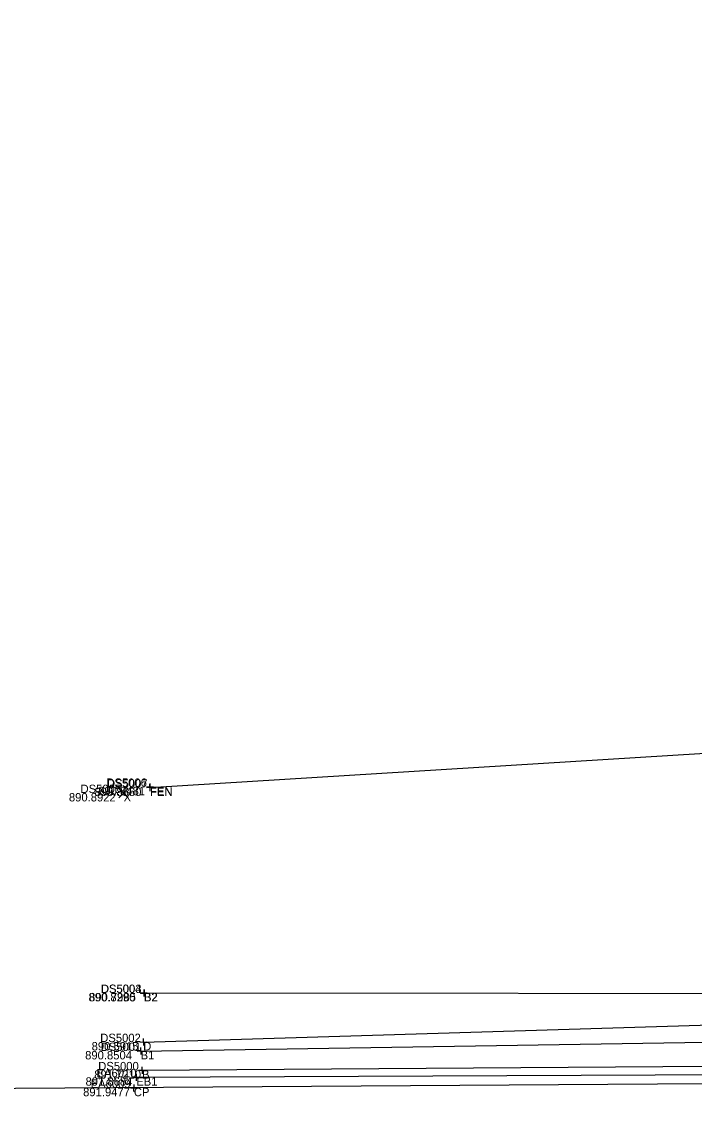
# Model space of a CAD drawing. Extents: x 179044 to 189691, y 286531 to 301257.
# Drawn here: x 179547.2 to 179643.4, y 300591.8 to 300746 of the extents above; entities that cross this region are included whole.
import ezdxf

# ---------------------------------------------------------------- set-up
doc = ezdxf.new("R2010")
doc.units = 0
for name, color, linetype in [('DR_X_Ditch', 7, 'Continuous'), ('PV_X_EOP', 7, 'Continuous'), ('PV_X_Shoulder_Aggregate', 7, 'Continuous'), ('RD_X_Fence', 7, 'Continuous'), ('SV_X_Break_Lines', 7, 'Continuous'), ('SV_X_Random_Point', 7, 'Continuous'), ('SV_X_Shot_Marker', 7, 'Continuous'), ('SV_X_Text_Comment', 7, 'Continuous'), ('SV_X_Text_Elevation', 7, 'Continuous'), ('SV_X_Text_Name', 7, 'Continuous')]:
    doc.layers.add(name, color=color, linetype=linetype)

msp = doc.modelspace()

# ---------------------------------------------------------------- linework, layer by layer
at = {"layer": 'DR_X_Ditch'}
msp.add_lwpolyline([(179564.56, 300599.96), (179672.34, 300603.26), (179771.17, 300605.49), (179880.34, 300606.44), (179984.94, 300607.33), (180077.95, 300608.96), (180127.19, 300616.84), (180132.04, 300619.57), (180144.29, 300623.54), (180155.55, 300629.29), (180160.46, 300633.55)], dxfattribs=at)
at = {"layer": 'PV_X_EOP'}
msp.add_lwpolyline([(179370.83, 300591.75), (179475.59, 300592.88), (179659.26, 300594.12), (179770.99, 300594.47), (179880.74, 300594.99), (179984.71, 300595.5), (180079.29, 300595.31), (180129.92, 300597.38), (180139.47, 300598.24), (180154.23, 300602.67), (180170.46, 300611.59), (180179.63, 300620.69), (180184.59, 300626.62), (180188.34, 300633.53), (180190.62, 300639.72), (180171.32, 300693.38), (180137.2, 300785.06), (180098.42, 300888.79)], dxfattribs=at)
at = {"layer": 'PV_X_Shoulder_Aggregate'}
msp.add_lwpolyline([(179563.56, 300594.92), (179658.99, 300595.36), (179770.6, 300596.26), (179881.56, 300597.13), (179984.26, 300597.36), (180079.14, 300597.32), (180129.31, 300600.3), (180139.96, 300601.42), (180153.02, 300605.12), (180169.97, 300613.88), (180177.63, 300623.69), (180181.65, 300635.11), (180183, 300649.24), (180167.77, 300692.69), (180134.64, 300784.2), (180095.48, 300888.51)], dxfattribs=at)
at = {"layer": 'RD_X_Fence'}
msp.add_line((179565.52, 300636.48), (179565.52, 300636.48), dxfattribs=at)
msp.add_lwpolyline([(180033.62, 300896.16), (180069.42, 300800.64), (180103.12, 300709.46), (180117.13, 300674.9), (180112.62, 300673.01), (180037.36, 300667.77), (179974.55, 300663.8), (179875.9, 300656.61), (179766.56, 300649.44), (179668.07, 300642.7), (179565.54, 300636.36)], dxfattribs=at)
at = {"layer": 'SV_X_Break_Lines'}
msp.add_line((179564.68, 300606.98), (179564.68, 300606.98), dxfattribs=at)
for points in [[(179564.64, 300606.99), (179671.77, 300606.92), (179771.09, 300608.91), (179880.6, 300615.61), (179986.88, 300616.02), (180078.03, 300615.52), (180124.74, 300624.49), (180128.29, 300624.22), (180137.3, 300629.12), (180148.46, 300633.71), (180154.5, 300636.5), (180146.31, 300651.24), (180135.97, 300673.81), (180118.54, 300716.07), (180095.91, 300772.35), (180076.61, 300824.96), (180047.5, 300900.2)], [(179564.19, 300598.68), (179770.81, 300601.94), (179880.33, 300600.56), (179984.71, 300602.17), (180076.3, 300602.51), (180129.45, 300605.47), (180133.82, 300610.67), (180143.54, 300612.06), (180154.91, 300619.36), (180168.81, 300625.75), (180172.9, 300631.66), (180174.53, 300641.07), (180168.31, 300660.62), (180157.54, 300688.57), (180123.87, 300779.29), (180087.27, 300883.22)], [(179564.39, 300595.92), (179672.75, 300596.68), (179770.46, 300597.56), (179880.51, 300598.54), (179984.7, 300599.01), (180076.34, 300598.77), (180129.48, 300602.03), (180135.94, 300603.81), (180151.81, 300606.88), (180162.98, 300612.72)]]:
    msp.add_lwpolyline(points, dxfattribs=at)
at = {"layer": 'SV_X_Random_Point'}
for p, q in [((179561.09, 300634.92), (179562.42, 300636.26)), ((179561.09, 300636.26), (179562.42, 300634.92))]:
    msp.add_line(p, q, dxfattribs=at)
at = {"layer": 'SV_X_Shot_Marker'}
for p, q in [((179565.02, 300636.48), (179566.02, 300636.48)), ((179566.04, 300636.39), (179565.04, 300636.33)), ((179565.57, 300635.86), (179565.51, 300636.86)), ((179565.52, 300636.98), (179565.52, 300635.98)), ((179565.52, 300636.48), (179565.52, 300636.48)), ((179565.54, 300636.36), (179565.54, 300636.36)), ((179564.64, 300607.49), (179564.64, 300606.49)), ((179564.68, 300607.48), (179564.68, 300606.48)), ((179564.14, 300606.99), (179565.14, 300606.99)), ((179564.18, 300606.98), (179565.18, 300606.98)), ((179564.64, 300606.99), (179564.64, 300606.99)), ((179564.68, 300606.98), (179564.68, 300606.98)), ((179564.06, 300599.95), (179565.06, 300599.98)), ((179564.55, 300600.46), (179564.58, 300599.46)), ((179564.56, 300599.96), (179564.56, 300599.96)), ((179563.69, 300598.67), (179564.69, 300598.69)), ((179564.18, 300599.18), (179564.2, 300598.18)), ((179564.19, 300598.68), (179564.19, 300598.68)), ((179564.38, 300596.42), (179564.39, 300595.42)), ((179563.06, 300594.92), (179564.06, 300594.93)), ((179563.56, 300595.42), (179563.57, 300594.42)), ((179563.56, 300594.92), (179563.56, 300594.92)), ((179563.89, 300595.92), (179564.89, 300595.92)), ((179564.39, 300595.92), (179564.39, 300595.92)), ((179562.72, 300593.43), (179563.72, 300593.39)), ((179563.2, 300592.91), (179563.24, 300593.91)), ((179563.22, 300593.41), (179563.22, 300593.41))]:
    msp.add_line(p, q, dxfattribs=at)

# ---------------------------------------------------------------- texts
at = {"layer": 'SV_X_Text_Comment'}
for s, p in [('FEN', (179565.52, 300635.28)), ('X', (179561.75, 300634.39)), ('FEN', (179565.54, 300635.16)), ('B2', (179564.64, 300605.79)), ('B2', (179564.68, 300605.78)), ('D', (179564.56, 300598.76)), ('B1', (179564.19, 300597.48)), ('EB1', (179563.56, 300593.72)), ('B', (179564.39, 300594.72)), ('CP', (179563.22, 300592.21))]:
    msp.add_text(s, height=1.2, dxfattribs=at).set_placement(p)
at = {"layer": 'SV_X_Text_Elevation'}
for s, p in [('890.8550', (179557.6, 300635.16)), ('890.8481', (179558.12, 300635.28)), ('890.8922', (179553.93, 300634.39)), ('890.8290', (179556.74, 300605.78)), ('890.7985', (179556.81, 300605.79)), ('890.5915', (179557.18, 300598.76)), ('890.8504', (179556.25, 300597.48)), ('891.8684', (179556.31, 300593.72)), ('891.7210', (179557.55, 300594.72)), ('891.9477', (179555.96, 300592.21))]:
    msp.add_text(s, height=1.2, dxfattribs=at).set_placement(p)
at = {"layer": 'SV_X_Text_Name'}
for s, p in [('DS5005', (179555.59, 300635.59)), ('DS5006', (179559.29, 300636.48)), ('DS5007', (179559.38, 300636.36)), ('DS5004', (179558.49, 300606.99)), ('DS5003', (179558.52, 300606.98)), ('DS5002', (179558.41, 300599.96)), ('DS5001', (179558.47, 300598.68)), ('DS5000', (179558.12, 300595.92)), ('EA6010', (179557.88, 300594.92)), ('EA6009', (179557.04, 300593.41))]:
    msp.add_text(s, height=1.2, dxfattribs=at).set_placement(p)

doc.saveas('drawing.dxf')
